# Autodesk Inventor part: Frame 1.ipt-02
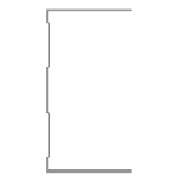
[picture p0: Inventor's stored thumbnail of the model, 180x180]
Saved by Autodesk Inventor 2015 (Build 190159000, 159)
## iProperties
Created: 2015-04
Part Number: Frame 1.ipt-02
Material: Aluminum 6061
Description: Kévin Novo
Document SubType Name: Modeling
Standard: Kevin
Designer: suporte
Standards Organization: Kevin
Language: en-US
Size Designation: (Unnamed 2)
Categories: <MemberInstance><Categories><Category DisplayName="Structural Shapes" InternalName="089c4875-fa83-4c05-b084-43b9cc11f5ed" Mnemonic="GRDR"><CategoryParameter Dis
Density: 2.7 g/cm^3
Appearance: Aluminum - Flat
IsCustomPart: 1
G_W: 50,000 mm
G_H: 75,000 mm
G_L: 470,645 mm
+BD433694-75ED-40FA-B604-0D23CBD579F9+CUTDETAIL3: Miter 67,49 deg
+5C76CBEB-8B41-4733-85A3-2AE3D2FC03BA+CUTDETAIL4: Miter 67,51 deg
_CCFamilyMember: 2
_CCFamilyDisplayName: Kévin - Kévin Novo
_FrameMemberDoc: Frame Member File
_Version: 15.0.0
_GetPNFromCC: 1
Author: suporte
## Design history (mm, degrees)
node "Start Plane"
node "End Plane"
sketch "Sketch"
  geometry: L1 (24.7, 37.5)-(24.7, 36.9); L2 (24.7, 36.9)-(-24.7, 36.9); L3 (-24.7, -36.9)-(24.7, -36.9); L4 (24.7, -36.9)-(24.7, -37.5); L5 (24.7, -37.5)-(-25.3, -37.5); L6 (-25.3, 37.5)-(24.7, 37.5); L7 (-24.7, 36.9)-(-24.7, 31.9); L8 (-24.7, 31.9)-(-23.3, 30.5); L9 (-23.3, 30.5)-(-23.3, 10.934); L10 (-23.3, 10.934)-(-24.7, 9.534); L11 (-24.7, 9.534)-(-24.7, -9.534); L12 (-24.7, -9.534)-(-23.3, -10.934); L13 (-23.3, -10.934)-(-23.3, -30.5); L14 (-23.3, -30.5)-(-24.7, -31.9); L15 (-24.7, -31.9)-(-24.7, -36.9); L16 (-25.3, -37.5)-(-25.3, -31.651); L17 (-25.3, -31.651)-(-23.9, -30.251); L18 (-23.9, -30.251)-(-23.9, -11.183); L19 (-23.9, -11.183)-(-25.3, -9.783); L20 (-25.3, -9.783)-(-25.3, 9.783); L21 (-25.3, 9.783)-(-23.9, 11.183); L22 (-23.9, 11.183)-(-23.9, 30.251); L23 (-23.9, 30.251)-(-25.3, 31.651); L24 (-25.3, 31.651)-(-25.3, 37.5); L25 (-25.3, 0)-(30.37, 0); 3 further points
  constraints: 50 end point, 10 point on line, 9 parallel, 5 perpendicular, 4 equal length, 3 midpoint, 3 vertical, 2 vertical alignment, 1 collinear, 1 horizontal, 1 horizontal alignment
  dimensions: "d3" = 0.6 distance of L1.start L1.end (= d6); "d5" = 75 distance between parallel lines of L5 L6; "d6" = 0.6 distance between parallel lines of L24 L7 (= d8); "d7" = 0.6 distance between parallel lines of L8 L23 (= d8); "d8" = 0.6 distance between parallel lines of L22 L9 (= d12); "Espessura" = 0.6 distance between parallel lines of L17 L14; "d10" = 0.6 distance between parallel lines of L13 L18 (= Espessura); "d11" = 0.6 distance between parallel lines of L12 L19 (= Espessura); "d12" = 0.6 distance between parallel lines of L21 L10 (= d11); "d13" = 5 distance of L2.end L7.end; "d15" = 135 deg angle of L9 L8; "d16" = 2 distance between parallel lines of L24 L9; "d17" = 50 distance of L6.start L1.start
extrude "Body" join sketch "Sketch" stored distance "d24" = 0.13; taper "d25" = 0 deg
node "Driven Length"
  sketch "Sketch10"
    geometry: L1 (0, 0)-(10, 0) reference
    constraints: 2 end point, 1 horizontal
  workplane "Work Plane7"
  sketch "Sketch11"
    geometry: L1 (-2, 5.175)-(12, 5.175) reference; L2 (-2, 475.82)-(12, 475.82) reference
    dimensions: "d27" = 470.64466 distance between parallel lines of L1 L2 (derived)
workplane "Work Plane10"
split "Split3"
workplane "Work Plane11"
split "Split4"
body "Solid1"
other parameters: "tamanho" = 481, "G_OFFSET_START" = -5.17512 [user parameter; used in 1 equation term], "G_OFFSET_END" = -5.18022 [user parameter; used in 1 equation term], "d22" = 5.17512 (= -G_OFFSET_START), "d23" = 475.81978 (= tamanho + G_OFFSET_END), "G_L" = 470.64466 (= d27) [user parameter], "d34" = 90 deg
